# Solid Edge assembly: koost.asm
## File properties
Author: Argo
Template: Normal.asm
Last saved by: haldur
Revision: 13
Application: Solid Edge
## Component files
tihvtikinnitus.par
aer2.par
paat2.par
aerukinnitusealus.par
aerukinnitus.par
mootorikinnitus.psm
tihvt_pikk.par
tihvt.par
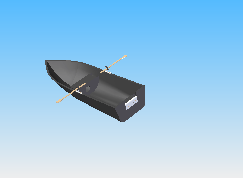
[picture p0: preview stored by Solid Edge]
